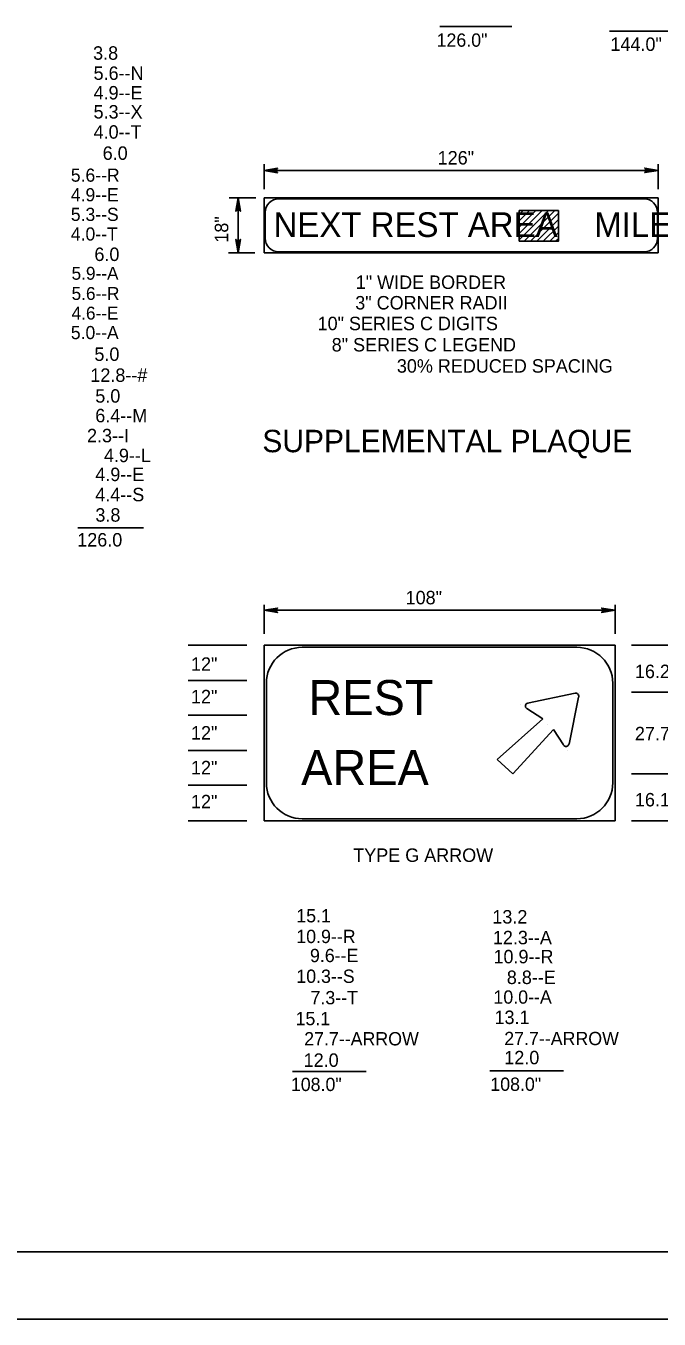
# Model space of a CAD drawing. Extents: x 649604 to 650509, y 298458 to 299646.
# Drawn here: x 649792 to 649933.2, y 298457.6 to 298746.1 of the extents above; entities that cross this region are included whole.
import ezdxf

# ---------------------------------------------------------------- set-up
doc = ezdxf.new("R2010")
doc.units = 0
for name, color, linetype in [('1', 7, 'Continuous'), ('2', 7, 'Continuous'), ('3', 7, 'Continuous'), ('PLT-BNDY', 7, 'Continuous')]:
    doc.layers.add(name, color=color, linetype=linetype)

# ---------------------------------------------------------------- blocks, each defined once
blk = doc.blocks.new('RARROW')
at = {"layer": '3'}
blk.add_lwpolyline([(-2.2695, 0.285), (-2.184875, 0.12075), (0, 0), (-2.2695, 0.285), (-2.38575, 0.384625), (0, 0), (-2.183125, -0.108), (-2.262875, -0.2705), (0, 0), (-2.38575, -0.379125), (-2.262875, -0.2705)], dxfattribs=at)

msp = doc.modelspace()

# ---------------------------------------------------------------- linework, layer by layer
at = {"layer": '1'}
for p, q in [((650430.31, 298472.63), (649644.31, 298472.63)), ((649644.31, 298472.63), (650230.31, 298472.63))]:
    msp.add_line(p, q, dxfattribs=at)
at = {"layer": '2'}
for p, q in [((649884.29, 298745.98), (649900.35, 298745.98)), ((649922.15, 298744.93), (649938.95, 298744.93)), ((649845.13, 298709.72), (649845.13, 298715.27)), ((649845.13, 298713.89), (649933, 298713.89)), ((649933, 298709.72), (649933, 298715.27)), ((649837.34, 298707.78), (649843.25, 298707.78)), ((649839.34, 298695.5), (649839.34, 298707.78)), ((649933, 298707.78), (649845.13, 298707.78)), ((649845.13, 298707.78), (649845.13, 298695.5)), ((649933, 298695.5), (649933, 298707.78)), ((649902.02, 298699.82), (649907.11, 298704.92)), ((649902.02, 298698.37), (649908.56, 298704.92)), ((649902.02, 298701.2), (649905.73, 298704.92)), ((649902.02, 298702.61), (649904.32, 298704.92)), ((649902.02, 298704.03), (649902.91, 298704.92)), ((649903.11, 298698.09), (649909.94, 298704.92)), ((649904.53, 298698.09), (649910.76, 298704.33)), ((649905.94, 298698.09), (649910.76, 298702.91)), ((649907.39, 298698.09), (649910.76, 298701.46)), ((649908.81, 298698.09), (649910.76, 298700.04)), ((649910.22, 298698.09), (649910.76, 298698.63)), ((649837.17, 298695.5), (649843.08, 298695.5)), ((649845.13, 298695.5), (649933, 298695.5)), ((649818.22, 298634.18), (649803.59, 298634.18)), ((649845.13, 298610.48), (649845.13, 298617.01)), ((649845.13, 298615.76), (649923.38, 298615.76)), ((649923.38, 298610.48), (649923.38, 298617.01)), ((649841.3, 298608.01), (649828.22, 298608.01)), ((649845.13, 298608.01), (649923.38, 298608.01)), ((649845.13, 298608.01), (649845.13, 298568.76)), ((649853.63, 298607.51), (649914.88, 298607.51)), ((649923.38, 298568.76), (649923.38, 298608.01)), ((649927.06, 298608.01), (649954.58, 298608.01)), ((649841.3, 298600.13), (649828.22, 298600.13)), ((649845.63, 298577.26), (649845.63, 298599.51)), ((649922.88, 298599.51), (649922.88, 298577.26)), ((649914.5, 298597.26), (649903.88, 298595.01)), ((649903.88, 298595.01), (649914.5, 298597.26)), ((649913.13, 298585.88), (649915.25, 298596.38)), ((649915.25, 298596.38), (649913.13, 298585.88)), ((649915.38, 298597.51), (649915.38, 298597.51)), ((649927.06, 298597.51), (649942.12, 298597.51)), ((649902.38, 298594.76), (649902.38, 298594.76)), ((649903.75, 298593.88), (649907.25, 298591.51)), ((649907.25, 298591.51), (649903.75, 298593.88)), ((649841.3, 298592.38), (649828.22, 298592.38)), ((649907.25, 298591.51), (649897.13, 298582.51)), ((649897.13, 298582.51), (649907.25, 298591.51)), ((649907.25, 298591.51), (649907.25, 298591.51)), ((649907.25, 298591.51), (649907.25, 298591.51)), ((649908.38, 298590.26), (649908.38, 298590.26)), ((649900.63, 298579.26), (649909.63, 298589.13)), ((649909.63, 298589.13), (649900.63, 298579.26)), ((649909.63, 298589.13), (649909.63, 298589.13)), ((649909.63, 298589.13), (649911.88, 298585.76)), ((649911.88, 298585.76), (649909.63, 298589.13)), ((649841.3, 298584.51), (649828.22, 298584.51)), ((649912.75, 298584.38), (649912.75, 298584.38)), ((649897.13, 298582.51), (649897.13, 298582.51)), ((649897.13, 298582.51), (649900.63, 298579.26)), ((649900.63, 298579.26), (649897.13, 298582.51)), ((649897.13, 298582.51), (649897.13, 298582.51)), ((649900.63, 298579.26), (649900.63, 298579.26)), ((649900.63, 298579.26), (649900.63, 298579.26)), ((649927.06, 298579.26), (649942.12, 298579.26)), ((649841.3, 298576.76), (649828.22, 298576.76)), ((649841.3, 298568.76), (649828.22, 298568.76)), ((649923.38, 298568.76), (649845.13, 298568.76)), ((649914.88, 298569.26), (649853.63, 298569.26)), ((649927.06, 298568.76), (649954.58, 298568.76)), ((649851.43, 298512.85), (649867.89, 298512.85)), ((649895.46, 298513.05), (649911.91, 298513.05))]:
    msp.add_line(p, q, dxfattribs=at)
for points in [[(649929.88, 298707.53), (649848.38, 298707.53)], [(649845.38, 298704.53), (649845.38, 298698.75)], [(649932.88, 298698.75), (649932.88, 298704.53)], [(649848.38, 298695.75), (649929.88, 298695.75)]]:
    msp.add_lwpolyline(points, dxfattribs=at)
msp.add_lwpolyline([(649902.02, 298698.09), (649910.76, 298698.09), (649910.76, 298704.92), (649902.02, 298704.92)], close=True, dxfattribs=at)
for centre, radius, start, end in [((649848.38, 298704.53), 3, 90, 180), ((649929.88, 298704.53), 3, 0, 90), ((649848.38, 298698.75), 3, 180, 270), ((649929.88, 298698.75), 3, 270, 0), ((649853.63, 298599.51), 8, 90, 180), ((649914.88, 298599.51), 8, 0, 90), ((649914.64, 298596.61), 0.659, 348.2602, 101.7398), ((649914.64, 298596.61), 0.659, 348.2602, 101.7398), ((649904.06, 298594.41), 0.659, 101.7398, 236.6838), ((649904.06, 298594.41), 0.659, 101.7398, 236.6838), ((649912.44, 298586.03), 0.659, 213.3162, 348.2602), ((649912.44, 298586.03), 0.659, 213.3162, 348.2602), ((649853.63, 298577.26), 8, 180, 270), ((649914.88, 298577.26), 8, 270, 0)]:
    msp.add_arc(centre, radius, start, end, dxfattribs=at)
at = {"layer": 'PLT-BNDY'}
msp.add_lwpolyline([(649604.31, 299051.63), (650445.31, 299051.63), (650445.31, 298457.63), (649604.31, 298457.63)], close=True, dxfattribs=at)

# ---------------------------------------------------------------- block references
at = {"layer": '2', "xscale": 1.2574347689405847, "yscale": 1.3092961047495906}
for p, rotation in [((649845.13, 298713.89), 180), ((649839.34, 298707.78), 89.99999999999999), ((649839.34, 298695.5), -90.00000000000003), ((649845.13, 298615.76), 180)]:
    msp.add_blockref('RARROW', p, dxfattribs=dict(at, rotation=rotation))
for p in [(649933, 298713.89), (649923.38, 298615.76)]:
    msp.add_blockref('RARROW', p, dxfattribs=at)

# ---------------------------------------------------------------- texts
at = {"layer": '2'}
for s, height, p in [('126.0"       ', 2.9663, (649883.59, 298741.48)), ('144.0"', 3, (649922.36, 298740.55)), (' 3.8    ', 3, (649805.87, 298738.58)), (' 5.6--N', 3, (649805.98, 298734.09)), (' 4.9--E', 3, (649805.98, 298729.72)), (' 5.3--X', 3, (649805.98, 298725.47)), (' 4.0--T', 3, (649805.98, 298720.97)), ('6.0', 3, (649809.12, 298716.25)), ('126"', 3, (649883.83, 298715.21)), ('    5.6--R', 2.931, (649797.66, 298711.37)), ('    4.9--E', 2.931, (649797.66, 298707)), ('    5.3--S', 2.931, (649797.66, 298702.62)), ('NEXT REST AREA    MILES', 5.5, (649847.23, 298699.05)), ('    4.0--T', 2.931, (649797.66, 298698.25)), (' 6.0', 3, (649806.16, 298693.68)), ('    5.9--A', 2.875, (649797.91, 298689.5)), ('    5.6--R', 2.875, (649797.91, 298685)), ('1" WIDE BORDER', 3, (649865.56, 298687.45)), ('3" CORNER RADII', 3, (649865.45, 298682.87)), ('    4.6--E', 2.875, (649797.91, 298680.62)), ('    5.0--A', 2.931, (649797.66, 298676.25)), ('   10" SERIES C DIGITS', 3, (649853.71, 298678.25)), ('   8" SERIES C LEGEND', 3, (649856.85, 298673.5)), (' 5.0', 3, (649806.16, 298671.4)), ('30% REDUCED SPACING', 3, (649874.73, 298668.77)), ('12.8--#', 3, (649806.37, 298666.72)), (' 5.0   ', 3, (649806.36, 298662.08)), (' 6.4--M', 3, (649806.36, 298657.7)), ('  2.3--I', 3, (649803.4, 298653.24)), ('SUPPLEMENTAL PLAQUE', 5, (649844.73, 298651.02)), ('4.9--L', 3, (649809.4, 298648.81)), (' 4.9--E', 3, (649806.36, 298644.58)), (' 4.4--S', 3, (649806.36, 298640.08)), (' 3.8', 3, (649806.38, 298635.53)), ('126.0', 3, (649803.45, 298629.99)), (' 108"', 3, (649875.57, 298617.09)), ('12"', 3, (649828.82, 298602.26)), ('16.2"', 3, (649927.82, 298600.63)), ('REST', 7.82, (649855, 298592.38)), ('12"', 3, (649828.82, 298595.01)), ('12"', 3, (649828.82, 298586.92)), ('27.7"', 3, (649927.82, 298586.76)), ('AREA', 7.82, (649853.38, 298576.76)), ('12"', 3, (649828.82, 298579.17)), ('12"', 3, (649828.82, 298571.59)), ('16.1"', 3, (649927.82, 298572.01)), ('TYPE G ARROW', 3, (649865, 298559.63))]:
    msp.add_text(s, height=height, dxfattribs=at).set_placement(p)
msp.add_text('18"', height=3, rotation=90, dxfattribs=at).set_placement((649837.13, 298697.77))
at = {"layer": '3'}
for s, height, p in [(' 15.1   ', 2.966, (649851.2, 298546.14)), (' 13.2   ', 3, (649894.91, 298545.88)), (' 10.9--R', 2.966, (649851.2, 298541.52)), (' 12.3--A', 3, (649895.03, 298541.25)), (' 9.6--E', 2.966, (649854.25, 298537.27)), (' 10.9--R', 3, (649895.16, 298537)), (' 10.3--S', 2.966, (649851.21, 298532.64)), (' 8.8--E', 3, (649898.14, 298532.38)), (' 7.3--T', 2.966, (649854.37, 298527.86)), (' 10.0--A', 2.966, (649895.17, 298528)), (' 15.1   ', 2.966, (649851.03, 298523.2)), (' 13.1', 3, (649895.39, 298523.46)), ('27.7--ARROW', 2.9663, (649854.06, 298518.69)), ('27.7--ARROW', 2.9663, (649898.68, 298518.75)), ('12.0       ', 3, (649898.69, 298514.48)), ('12.0        ', 3, (649853.94, 298513.91)), ('108.0"       ', 2.9663, (649851.09, 298508.51)), ('108.0"       ', 2.9663, (649895.57, 298508.55))]:
    msp.add_text(s, height=height, dxfattribs=at).set_placement(p)

doc.saveas('drawing.dxf')
